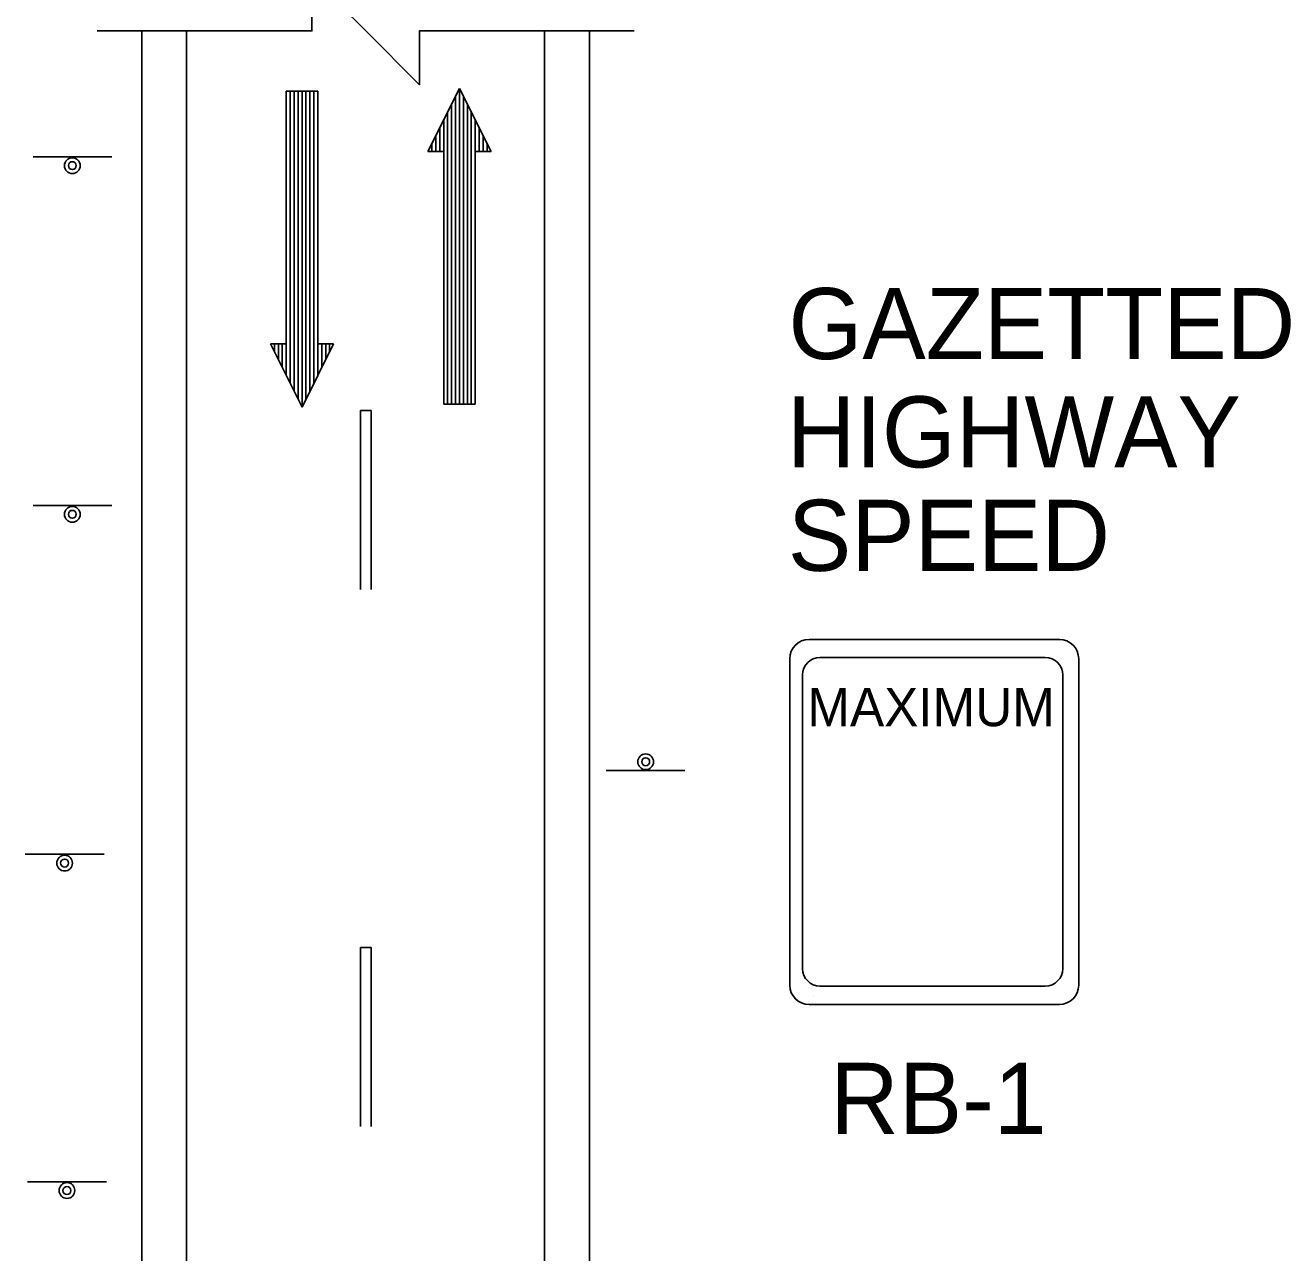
# Model space of a CAD drawing. Extents: x 1806 to 2022, y 110 to 389.
# Drawn here: x 1874.57 to 1908.76, y 322.2 to 355.36 of the extents above; entities that cross this region are included whole.
import ezdxf

# ---------------------------------------------------------------- set-up
doc = ezdxf.new("R2010")
doc.units = 0
for name, color, linetype in [('Level 10', 7, 'Continuous'), ('Level 2', 7, 'Continuous'), ('Level 20', 7, 'Continuous'), ('Level 44', 7, 'Continuous'), ('Level 50', 7, 'Continuous')]:
    doc.layers.add(name, color=color, linetype=linetype)

msp = doc.modelspace()

# ---------------------------------------------------------------- linework, layer by layer
at = {"layer": 'Level 10'}
for p, q in [((1877.715, 296.293), (1877.715, 355.206)), ((1878.925, 296.293), (1878.925, 355.206)), ((1888.603, 296.177), (1888.603, 355.206)), ((1889.812, 296.293), (1889.812, 355.206))]:
    msp.add_line(p, q, dxfattribs=at)
at = {"layer": 'Level 2'}
for p, q in [((1883.628, 344.954), (1883.628, 340.116)), ((1883.918, 344.954), (1883.628, 344.954)), ((1883.918, 340.116), (1883.918, 344.954)), ((1883.628, 330.44), (1883.628, 325.602)), ((1883.918, 330.44), (1883.628, 330.44)), ((1883.918, 325.602), (1883.918, 330.44))]:
    msp.add_line(p, q, dxfattribs=at)
at = {"layer": 'Level 20'}
msp.add_lwpolyline([(1876.511, 355.206), (1882.317, 355.206), (1882.317, 356.656), (1883.768, 355.206), (1885.22, 353.754), (1885.22, 355.206), (1891.025, 355.206)], dxfattribs=at)
at = {"layer": 'Level 44'}
for p, q in [((1876.912, 351.806), (1874.779, 351.806)), ((1876.912, 342.386), (1874.779, 342.386)), ((1895.749, 338.767), (1902.514, 338.767)), ((1895.227, 329.426), (1895.227, 338.245)), ((1896.045, 338.279), (1902.134, 338.279)), ((1903.037, 338.245), (1903.037, 329.426)), ((1895.576, 329.872), (1895.576, 337.81)), ((1902.605, 337.81), (1902.605, 329.872)), ((1890.264, 335.222), (1892.397, 335.222)), ((1876.703, 332.962), (1874.57, 332.962)), ((1895.576, 329.87), (1895.576, 329.872)), ((1895.227, 329.423), (1895.227, 329.426)), ((1902.134, 329.402), (1896.045, 329.402)), ((1895.868, 329.119), (1895.868, 329.119)), ((1902.514, 328.901), (1895.749, 328.901)), ((1876.766, 324.115), (1874.633, 324.115))]:
    msp.add_line(p, q, dxfattribs=at)
for centre, radius in [((1875.841, 351.567), 0.213), ((1875.841, 351.567), 0.107), ((1875.841, 342.147), 0.213), ((1875.841, 342.147), 0.107), ((1891.335, 335.461), 0.213), ((1891.335, 335.461), 0.107), ((1875.632, 332.723), 0.213), ((1875.632, 332.723), 0.107), ((1875.695, 323.876), 0.213), ((1875.695, 323.876), 0.107)]:
    msp.add_circle(centre, radius, dxfattribs=at)
for centre, radius, start, end in [((1895.749, 338.244), 0.522, 90, 180), ((1902.514, 338.244), 0.522, 360, 90), ((1896.045, 337.809), 0.47, 90, 180), ((1902.134, 337.809), 0.47, 360, 90), ((1896.045, 329.87), 0.47, 180, 270), ((1902.134, 329.87), 0.47, 270, 360), ((1895.749, 329.424), 0.522, 180, 270), ((1902.514, 329.424), 0.522, 270, 360)]:
    msp.add_arc(centre, radius, start, end, dxfattribs=at)
at = {"layer": 'Level 50'}
for p, q in [((1881.621, 346.752), (1881.621, 353.579)), ((1882.474, 353.579), (1881.621, 353.579)), ((1881.621, 345.899), (1881.621, 353.579)), ((1881.728, 345.685), (1881.728, 353.579)), ((1881.834, 345.472), (1881.834, 353.579)), ((1881.941, 345.259), (1881.941, 353.579)), ((1882.048, 345.045), (1882.048, 353.579)), ((1882.154, 345.259), (1882.154, 353.579)), ((1882.261, 345.472), (1882.261, 353.579)), ((1882.368, 345.685), (1882.368, 353.579)), ((1882.474, 346.752), (1882.474, 353.579)), ((1882.474, 345.899), (1882.474, 353.579)), ((1886.303, 353.653), (1885.45, 351.947)), ((1886.303, 353.653), (1886.303, 345.12)), ((1886.303, 353.653), (1887.156, 351.947)), ((1886.196, 353.44), (1886.196, 345.12)), ((1886.41, 353.44), (1886.41, 345.12)), ((1885.983, 353.013), (1885.983, 345.12)), ((1886.09, 353.226), (1886.09, 345.12)), ((1886.516, 353.226), (1886.516, 345.12)), ((1886.623, 353.013), (1886.623, 345.12)), ((1885.77, 352.586), (1885.77, 351.947)), ((1885.876, 352.8), (1885.876, 345.12)), ((1886.73, 352.8), (1886.73, 345.12)), ((1886.836, 352.586), (1886.836, 351.947)), ((1885.663, 352.373), (1885.663, 351.947)), ((1886.943, 352.373), (1886.943, 351.947)), ((1885.45, 351.947), (1885.876, 351.947)), ((1885.556, 352.16), (1885.556, 351.947)), ((1885.876, 351.947), (1885.876, 345.12)), ((1886.73, 351.947), (1886.73, 345.12)), ((1886.73, 351.947), (1887.156, 351.947)), ((1887.05, 352.16), (1887.05, 351.947)), ((1882.048, 345.045), (1881.194, 346.752)), ((1881.621, 346.752), (1881.194, 346.752)), ((1881.301, 346.539), (1881.301, 346.752)), ((1881.408, 346.325), (1881.408, 346.752)), ((1881.514, 346.112), (1881.514, 346.752)), ((1882.048, 345.045), (1882.901, 346.752)), ((1882.901, 346.752), (1882.474, 346.752)), ((1882.581, 346.112), (1882.581, 346.752)), ((1882.688, 346.325), (1882.688, 346.752)), ((1882.794, 346.539), (1882.794, 346.752)), ((1885.876, 345.12), (1886.73, 345.12))]:
    msp.add_line(p, q, dxfattribs=at)

# ---------------------------------------------------------------- texts
at = {"layer": 'Level 10'}
for s, p in [('GAZETTED', (1895.194, 346.34)), ('HIGHWAY', (1895.151, 343.414)), ('SPEED', (1895.177, 340.619)), ('RB-1', (1896.32, 325.407))]:
    msp.add_text(s, height=1.92, rotation=360, dxfattribs=at).set_placement(p)
at = {"layer": 'Level 44'}
msp.add_text('MAXIMUM', height=1.035, rotation=360, dxfattribs=at).set_placement((1895.703, 336.422))

doc.saveas('drawing.dxf')
